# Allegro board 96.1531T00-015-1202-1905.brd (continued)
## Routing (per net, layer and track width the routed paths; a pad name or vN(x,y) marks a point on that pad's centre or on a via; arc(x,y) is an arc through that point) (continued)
N30748963: length 5.7
  TOP w0.254: U804.29 50.21,20.83 R2928.2 49.87,20.72 49.54,20.38 49.54,18.88 49.29,18.62 R2927.1
N31274082:
  vias: v1(74.73,71.53) v1(74.73,70.89) v1(74.73,70.26) v1(74.73,69.62) v1(75.36,71.53) v1(75.36,70.89) v1(75.36,70.26) v1(75.36,69.62) v1(76,71.53) v1(76,70.89) v1(76,70.26) v1(76,69.62)
N31338205:
  vias: v1(77.75,67.64) v1(77.75,67.01) v1(77.75,66.37) v1(77.75,65.74) v1(78.38,67.64) v1(78.38,67.01) v1(78.38,66.37) v1(78.38,65.74) v1(79.02,67.64) v1(79.02,67.01) v1(79.02,66.37) v1(79.02,65.74)
N312711240: length 1.8
  TOP w0.102: U1309.8 v1(54.97,55.16)
  BOTTOM w0.102: DO.1 v1(54.97,55.16)

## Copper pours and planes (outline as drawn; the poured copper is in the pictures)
3V3 on TOP (solid shape): 86.8,7.62 86.04,7.62 86.04,9.8 86.8,9.8
GND on TOP (solid shape): 42.2,31.71 42.2,29.22 40.73,29.22 40.22,29.73 40.22,31.21 40.8,31.79 42.12,31.79
GND on TOP (solid shape): 42.2,24.86 42.2,22.37 40.73,22.37 40.22,22.87 40.22,24.35 40.8,24.93 42.12,24.93
GND on TOP (solid shape): 61.71,31.31 61.71,29.83 61.12,29.25 59.8,29.25 59.72,29.33 59.72,31.82 61.2,31.82
GND on TOP (solid shape): 61.71,24.45 61.71,22.98 61.12,22.39 59.8,22.39 59.72,22.47 59.72,24.96 61.2,24.96
GND on TOP (solid shape): 44.03,50.93 42.55,49.46 40.72,49.46 40.63,49.56 40.63,50.4 40.72,50.5 41.42,50.5 42.63,51.71 44.03,51.71
GND on TOP (solid shape): 44.03,57.48 44.03,56.64 42.61,56.64 41.38,57.87 40.85,57.87 40.65,58.07 40.65,58.81 40.72,58.88 42.63,58.88
GND on TOP: 99.49,0.51 76.76,0.51 76.76,4.5 70,11.26 63.24,4.5 63.24,0.51 0.51,0.51 0.51,63.24 4,63.24 8.78,65.22 10.76,70 10.76,74.49 85.74,74.49 85.74,70 92.5,63.24 99.26,70 99.26,74.49 116.49,74.49 116.49,21.51 99.49,21.51 ; 5 cut-outs
GND on BOTTOM, MID1(L2), MID2(L3): 99.49,0.51 76.76,0.51 76.76,4.5 70,11.26 63.24,4.5 63.24,0.51 0.51,0.51 0.51,63.24 4,63.24 8.78,65.22 10.76,70 10.76,74.49 85.74,74.49 85.74,70 92.5,63.24 99.26,70 99.26,74.49 116.49,74.49 116.49,21.51 99.49,21.51
VDDL on TOP (solid shape): 50.67,50.55 50.67,48.67 43.59,41.58 35.2,41.58 34.57,42.21 34.57,44.3 34.72,44.45 43.74,44.45 49.28,49.99 49.28,50.75 48.92,51.1 47.4,51.1 47.37,51.13 47.37,51.36 47.42,51.41 49.81,51.41
VDDR on TOP (solid shape): 50.73,68.32 50.73,57.96 49.71,56.95 47.57,56.95 47.55,56.97 47.55,57.2 47.62,57.28 48.87,57.28 49.08,57.49 49.08,66.5 48,67.59 43.81,67.59 43.41,68 43.41,69.52 43.64,69.75 49.3,69.75
VDDRA on TOP (solid shape): 57.9,31.35 57.9,30.95 56.42,29.47 56.12,29.47 56.12,31.34 56.28,31.51 57.75,31.51
VDDRA on TOP (solid shape): 58.53,27.75 58.53,26.43 58.51,26.41 58.15,26.41 57.82,26.74 54.77,26.74 54.77,27.45 57.82,27.45 58.18,27.8 58.48,27.8
VDDRA on TOP (solid shape): 58.39,22.73 58.39,10.9 59.08,10.21 62.97,10.21 63.14,10.03 63.14,8.69 62.48,8.03 54.99,8.03 54.74,8.28 54.74,10.03 56.57,11.86 56.57,21.64 56.11,22.09 56.11,24.58 56.55,24.58
VDDRA on MID2(L3): 56.21,27.38 56.21,19.48 56.62,19.08 58.27,19.08 60.68,21.49 60.68,29.21 58.04,31.85 56.31,31.85 56.08,31.62 56.08,30.3 56.37,30.02 56.98,30.02 58.42,28.57 58.42,25.02 58.34,24.94 58.09,24.94 58.01,25.02 58.01,27.61 57.86,27.76 56.59,27.76
VDDSB on TOP (solid shape): 45.8,31.02 45.8,29.47 45.4,29.47 44.02,30.85 44.02,31.35 44.18,31.51 45.32,31.51
VDDSB on TOP (solid shape): 44.1,27.45 47.15,27.45 47.15,26.74 44.1,26.74 43.75,26.38 43.44,26.38 43.39,26.43 43.39,27.75 43.42,27.78 43.77,27.78
VDDSB on TOP (solid shape): 45.64,8.92 44.86,8.13 36.47,8.13 36.27,8.33 36.27,9.6 36.58,9.91 42.88,9.91 43.69,10.72 43.69,22.91 45.22,24.45 45.64,24.45
VDDSB on MID2(L3): 45.52,27.13 45.52,18.49 45.09,18.06 42.24,18.06 41.05,19.25 41.05,28.96 43.68,31.59 45.6,31.59 45.87,31.32 45.87,30.02 45.61,29.76 44.75,29.76 43.31,28.32 43.31,24.77 43.38,24.69 43.64,24.69 43.71,24.77 43.71,27.36 43.87,27.51 45.14,27.51
MLA on TOP (solid shape): 40.11,49.66 40.11,48.72 40.09,48.7 39.2,48.7 38.92,48.42 37.24,48.42 36.99,48.67 36.99,49.76 40.01,49.76
MLB on TOP (solid shape): 41.15,52.58 42.02,52.58 42.04,52.56 42.04,51.54 41.26,50.75 34.5,50.75 33.48,49.73 33.48,44.86 33.15,44.53 30.86,44.53 30.63,44.75 30.63,51.71 32.44,53.52 40.21,53.52
MRA on TOP (solid shape): 34.99,57.59 41.26,57.59 42.04,56.8 42.04,55.79 42.02,55.76 41.15,55.76 40.21,54.82 31.34,54.82 30.53,55.63 30.53,58.88 31.01,59.36 33.22,59.36
MRB on TOP (solid shape): 39.2,59.65 40.09,59.65 40.11,59.62 40.11,58.68 40.01,58.58 36.99,58.58 36.99,59.67 37.24,59.93 38.92,59.93
Net_11 on TOP (solid shape): outline of 202 points within -49.26,77.74 -44.74,82.27
Net_12 on BOTTOM (solid shape): outline of 202 points within -44.26,77.74 -39.74,82.27
Net_14 on TOP (solid shape): outline of 202 points within -49.26,-78.26 -44.74,-73.73
Net_15 on BOTTOM (solid shape): outline of 202 points within -44.26,-78.26 -39.74,-73.73
Net_17 on BOTTOM (solid shape): outline of 202 points within 122.74,-78.26 127.26,-73.74
Net_18 on TOP (solid shape): outline of 202 points within 127.74,-78.26 132.26,-73.74
Net_20 on BOTTOM (solid shape): outline of 202 points within 122.74,77.74 127.26,82.26
Net_21 on TOP (solid shape): outline of 202 points within 127.74,77.74 132.26,82.26
PWR_3V3 on TOP (solid shape): 88.01,24.21 88.01,10.29 87.91,10.19 86.21,10.19 86.11,10.29 86.11,24.23 86.33,24.46 87.76,24.46
PWR_3V3 on TOP (solid shape): 53.87,36.37 53.87,35.1 53.82,35.05 53.24,35.05 53.04,34.85 53.04,34.26 52.9,34.13 52.43,34.13 52.38,34.18 52.38,35.65 52.76,36.02 52.76,36.55 52.83,36.63 53.62,36.63
PWR_3V3 on MID2(L3): 55.8,18.82 55.5,18.52 54.36,18.52 53.19,17.35 53.19,15.27 52.58,14.66 48.01,14.66 46.15,16.51 46.15,43.51 59.79,57.15 74.98,57.15 88.8,43.33 88.8,23.37 88.47,23.04 86.84,23.04 86.49,23.39 86.49,37.16 72.39,51.26 63.8,51.26 55.8,43.26
PWR_24V on TOP (solid shape): 36.2,47.24 36.2,45.49 35.99,45.29 34.44,45.29 34.21,45.52 34.21,47.17 34.37,47.32 36.12,47.32
PWR_24V on TOP (solid shape): 38.48,7.29 38.48,5.64 38.23,5.38 36.35,5.38 36.27,5.46 36.27,7.21 36.47,7.42 38.35,7.42
PWR_24V on TOP (solid shape): 63.55,12.98 63.55,11.23 63.35,11.02 61.47,11.02 61.34,11.15 61.34,12.8 61.59,13.06 63.47,13.06
PWR_24V on TOP (solid shape): 65.94,67.77 65.94,65 65.38,64.44 58.8,64.44 58.34,64.9 58.34,67.74 58.78,68.17 65.53,68.17
PWR_24V on TOP (solid shape): 42.57,69.62 42.57,67.74 42.44,67.61 38.05,67.61 37.74,67.92 37.74,69.57 38,69.82 42.37,69.82
PWR_24V on MID2(L3): 23.37,12.95 33.83,2.49 56.74,2.49 63.6,9.35 63.6,12.98 62.97,13.61 39.4,13.61 36.25,16.76 36.25,60.12 38.38,62.26 60.68,62.26 62.08,63.65 62.08,69.72 61.01,70.79 31.62,70.79 23.37,62.53
N29689929 on TOP (solid shape): 6.64,60.77 6.64,55.63 6.41,55.4 4.89,55.4 4.64,55.65 4.64,60.43 5.22,61.01 6.4,61.01
N29689929 on TOP (solid shape): 24.05,49.28 24.05,44.75 23.8,44.5 18.11,44.5 17.4,45.21 5.18,45.21 4.67,45.72 4.67,49.2 5.32,49.85 23.48,49.85
N29689929 on MID2(L3) (solid shape): 7.21,57.2 7.21,56.03 6.5,55.32 5.03,55.32 4.42,54.71 4.42,51.13 6.71,48.84 6.71,45.85 6.17,45.31 4.24,45.31 1.63,47.93 1.63,56.26 3,57.63 6.78,57.63
N29690282 on TOP (solid shape): 6.83,44.23 6.83,38.81 6.55,38.53 5.18,38.53 4.75,38.96 4.75,44.23 5.13,44.62 6.45,44.62
N29690282 on TOP (solid shape): 24.1,58.88 24.1,51.77 22.89,50.55 5.31,50.55 4.8,51.05 4.8,54.31 5.23,54.74 16.81,54.74 18.06,55.98 18.06,58.95 18.26,59.16 23.83,59.16
N29690282 on MID2(L3) (solid shape): 10.16,51.74 10.16,43.71 8.46,42.01 5,42.01 4.62,42.39 4.62,44.55 5.05,44.98 6.6,44.98 7.14,45.52 7.14,48.95 4.75,51.33 4.75,54.51 5.23,54.99 6.91,54.99
N29721066 on TOP (solid shape): 71.27,33.1 71.27,26.59 66.34,21.67 64.77,21.67 64.72,21.72 64.72,27.13 65.66,28.07 66.88,28.07 67.74,28.93 67.74,33.15 68.02,33.43 70.94,33.43
N29721090 on TOP (solid shape): 103.23,26.8 112.06,26.8 112.29,26.57 112.29,22.94 111.68,22.33 109.73,22.33 108.06,23.99 99.17,23.99 93.14,30.02 77.55,30.02 77.34,30.23 77.34,34.77 78.11,35.53 94.49,35.53
N29721182 on TOP (solid shape): 70.92,44.4 70.92,40.92 67.36,37.36 67.36,29.06 66.85,28.55 64.74,28.55 64.67,28.63 64.67,41.33 68.07,44.73 70.59,44.73
N29721210 on TOP (solid shape): 80.54,44.73 80.54,41.22 81.38,40.39 98.78,40.39 104.42,34.75 104.42,30.63 105.18,29.87 111.84,29.87 112.09,29.62 112.09,27.71 111.61,27.23 103.61,27.23 94.49,36.35 80.62,36.35 77.06,39.9 77.06,44.75 77.5,45.19 80.09,45.19
N29736051 on TOP (solid shape): 24.28,34.29 24.28,28.07 23.15,26.93 5.12,26.93 4.9,27.16 4.9,29.06 5.15,29.31 18.52,29.31 19.99,30.78 19.99,33.88 20.57,34.47 24.1,34.47
N29736075 on TOP (solid shape): 24.16,25.1 24.16,19.96 23.98,19.79 7.09,19.79 4.95,21.93 4.95,25.78 5.27,26.11 6.35,26.11 8.51,23.95 12.42,23.95 14.76,26.29 22.96,26.29
N29738065 on TOP (solid shape): 37.21,33.99 37.21,28.78 36.78,28.35 31.09,28.35 30.4,29.03 30.4,34.49 30.63,34.72 36.47,34.72
N29738250 on TOP (solid shape): 37.24,25.91 37.24,20.55 36.22,19.53 31.32,19.53 30.48,20.37 30.48,25.45 31.06,26.04 37.11,26.04
N30706789 on TOP (solid shape): 112.14,33.17 112.14,30.45 111.91,30.23 110.13,30.23 109.55,30.81 109.55,32.66 109.32,32.89 105.59,32.89 105.31,33.17 105.31,34.92 105.46,35.08 110.24,35.08
N30708243 on TOP (solid shape): 12.7,31.62 12.7,30.15 12.19,29.64 5.2,29.64 4.85,30 4.85,31.51 5.33,32 12.32,32
N31274082 on TOP (solid shape): 76.45,72.69 76.45,69.37 76.2,69.11 70.59,69.11 70.26,69.44 70.26,72.59 70.74,73.08 76.07,73.08
N31274082 on MID2(L3): 72.42,71.91 76.07,71.91 76.48,71.5 76.48,65 93.9,47.57 93.9,15.9 93.09,15.09 90.42,15.09 89.79,15.72 89.79,43.99 72.01,61.77 72.01,71.5
N31338205 on TOP (solid shape): 79.65,67.77 79.65,65.63 79.02,65 70.66,65 70.13,65.53 70.13,67.89 70.87,68.63 78.79,68.63
N31338205 on MID2(L3): 77.93,68.45 81.08,68.45 98.78,50.75 98.78,13.89 95.4,10.52 92.33,10.52 91.52,11.33 91.52,12.95 94.51,15.95 94.51,47.8 77.01,65.3 77.01,67.54

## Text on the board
BOTTOM: BOTTOM
Board Geometry/Soldermask Bottom: BOTTOM_SOLDERMASK
Package Geometry/Pastemask Bottom: Bottom Origin | Bottom Side Reflow
Ref Des/Silkscreen Bottom: BOTTOM_SILKSCREEN
User.Comments: CR_UNNAMED_2 | 12.PCB Outline Dimension Tol: | 10.MATERIAL : | 11.PLATING : | 1. PCB VENDOR MUST BE UL  QUALIFIED | 2. BOARD MUST BE IDENTIFIED WITH APPROPRIATE VENDOR UL IDENTIFACTION MARK,DATE CODE | 3. PCB MATERIAL UL FLAMMIBILITY RATING(94V-0 MINIMUM) | 4. ALL DIMESION TOLERANCE AS BELOW UNLESS OTHERWISE SPECIFIED. | 5. PCB LAYERS : | 6. PCB THICKNESS : | 7. | 8. TOP SIDE SILKSCREEN : | 9. SOLDER MASK : | NOTES: | TRACE WIDTHS TO BE FINISHED SIZES+/-1MIL | BOTTOM SIDE SILKSCREEN: | OSP 0.2-0.6um[8-24uinch]) | FR4 | 4 LAYERs | GREEN | 1.6 mm+/-0.15 mm | TG: | ,BOTH SIDES | WHITE | 150 | ROUTING : | CELSIUS | +/- 0.13mm | 0.7mil(min) | Prepreg | Copper | Core | Top(L1) | Mid2(L3) | Bot(L4) | Mid1(L2) | 1.8 +/-0.4 mil(H/1oz Finished) | 3.23 +/-0.5 mil | 3.937 +/-0.2 mil(1oz) | 40.189+/-2.9 mil | (0.4~1.2mil) | (63.0+/-6 mil) | 1.6+/-0.15mm
TOP: TOP
Board Geometry/Soldermask Top: TOP_SOLDERMASK
Package Geometry/Pastemask Top: Top Side Reflow | Top Origin
Ref Des/Silkscreen Top: 1 | REV.0 GP | 96.1531 | 803524 | Label | TOP_SILKSCREEN
MID1(L2): MID1(L2)
MID2(L3): MID2(L3)
PAGE_OUTLINE: Scale 1000mil | Layer name | PCB P/N | Rev. | Foxconn/CNSBG | 308.03524 | 015
DISPLAY_TOP: 1 | Bottom Side Reflow | 0 degree | Top Side Reflow | 180 degree | Cavity_Number | *Reference CNSBG Break-Away rule | Unit:MM
User.13: MID3(L4)
User.14: MID4(L5)
User.15: MID5(L6)
User.16: MID6(L7)
User.17: MID7(L8)
User.18: MID8(L9)
User.19: MID9(L10)
User.20: MID11(L12)
User.21: MID12(L13)
User.24: BOTTOM_PASTE
User.25: TOP_PASTE
User.28: NCDRILL
User.30: BOTTOM_ASSEMBLY
User.31: TOP_ASSEMBLY
User.32: BOTTOM_ASSEMBLY
User.41: FIGURE | SIZE | 10.0 | 12.0 | 44.0 | 71.0 | 165.0 | 157.0 | 50.0x33.0 | DRILL CHART: TOP to BOTTOM | ALL UNITS ARE IN MILS | TOLERANCE | +3.0/-3.0 | +4.0/-0.0 | +4.0/-4.0 | PLATED | NON-PLATED | QTY | 658 | 13 | 8 | 4 | 2 | 6
